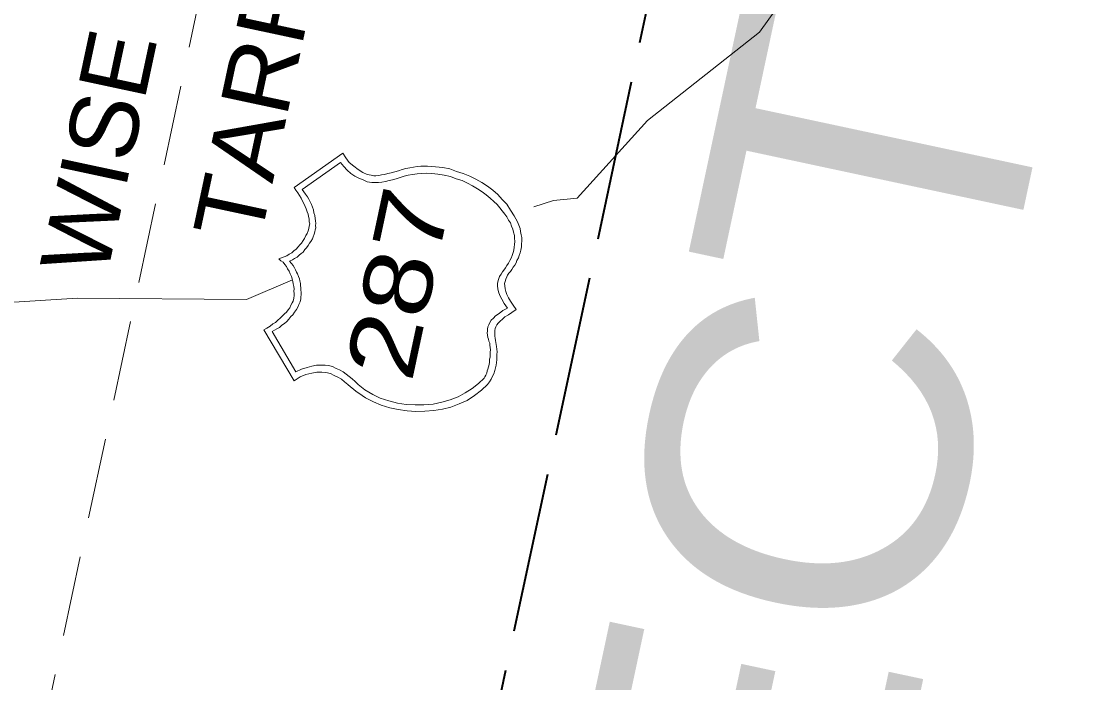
# Model space of a CAD drawing. Extents: x 2363411 to 2369126, y 6976878 to 6988319.
# Drawn here: x 2365792.5 to 2365871.2, y 6977067.2 to 6977116.7 of the extents above; entities that cross this region are included whole.
import ezdxf

# ---------------------------------------------------------------- set-up
doc = ezdxf.new("R2010")
doc.units = 0
doc.header["$LTSCALE"] = 2
doc.linetypes.add('LONG_DASHED', pattern=[7.5, 6, -1.5])
doc.linetypes.add('MEDIUM_DASHED', pattern=[4.5, 3, -1.5])
doc.layers.add('62', color=7, linetype='Continuous', lineweight=13)
doc.layers.add('63', color=7, linetype='Continuous', lineweight=13)

msp = doc.modelspace()

# ---------------------------------------------------------------- linework, layer by layer
at = {"layer": '62', "linetype": 'MEDIUM_DASHED'}
msp.add_line((2365864.629, 6977393.47), (2365770.962, 6976955.102), dxfattribs=at)
at = {"layer": '62'}
for p, q in [((2365832.332, 6977103.289), (2365830.869, 6977102.796)), ((2365809.372, 6977095.885), (2365812.816, 6977097.358))]:
    msp.add_line(p, q, dxfattribs=at)
for points in [[(2365832.332, 6977103.289), (2365834.117, 6977103.46), (2365839.362, 6977109.264), (2365847.746, 6977115.874), (2365856.16, 6977127.585), (2365865.436, 6977136.53), (2365870.448, 6977142.431)], [(2365812.924, 6977089.788), (2365810.657, 6977093.611), (2365810.894, 6977093.742), (2365811.129, 6977093.878), (2365811.326, 6977094.044), (2365811.534, 6977094.158), (2365811.706, 6977094.329), (2365811.878, 6977094.477), (2365812.048, 6977094.624), (2365812.222, 6977094.794), (2365812.366, 6977094.927), (2365812.474, 6977095.11), (2365812.598, 6977095.264), (2365812.685, 6977095.454), (2365812.789, 6977095.615), (2365812.865, 6977095.761), (2365812.912, 6977095.982), (2365812.933, 6977096.184), (2365812.94, 6977096.32), (2365812.906, 6977096.49), (2365812.924, 6977096.671), (2365812.917, 6977096.854), (2365812.864, 6977097.047), (2365812.832, 6977097.218), (2365812.781, 6977097.413), (2365812.731, 6977097.608), (2365812.632, 6977097.79), (2365812.56, 6977097.99), (2365812.441, 6977098.177), (2365812.362, 6977098.355), (2365812.231, 6977098.496), (2365812.107, 6977098.663), (2365811.943, 6977098.766), (2365811.79, 6977098.911), (2365811.989, 6977098.985), (2365812.191, 6977099.056), (2365812.393, 6977099.152), (2365812.554, 6977099.255), (2365812.763, 6977099.372), (2365812.91, 6977099.522), (2365813.077, 6977099.65), (2365813.224, 6977099.805), (2365813.349, 6977099.96), (2365813.494, 6977100.091), (2365813.605, 6977100.296), (2365813.703, 6977100.435), (2365813.799, 6977100.67), (2365813.9, 6977100.808), (2365813.989, 6977101.02), (2365814.026, 6977101.196), (2365814.061, 6977101.35), (2365814.104, 6977101.548), (2365814.064, 6977101.693), (2365814.063, 6977101.902), (2365814.012, 6977102.097), (2365813.98, 6977102.263), (2365813.902, 6977102.442), (2365813.835, 6977102.663), (2365813.757, 6977102.841), (2365813.663, 6977103.045), (2365813.565, 6977103.229), (2365813.452, 6977103.458), (2365813.331, 6977103.645), (2365813.214, 6977103.854), (2365813.071, 6977104.045), (2365812.933, 6977104.26), (2365816.564, 6977106.82), (2365816.79, 6977106.471), (2365817.058, 6977106.115), (2365817.389, 6977105.838), (2365817.729, 6977105.606), (2365818.071, 6977105.371), (2365818.409, 6977105.231), (2365818.695, 6977105.168), (2365818.893, 6977105.126), (2365819.057, 6977105.136), (2365819.27, 6977105.16), (2365819.459, 6977105.189), (2365819.699, 6977105.23), (2365819.943, 6977105.29), (2365820.184, 6977105.355), (2365820.455, 6977105.438), (2365820.746, 6977105.511), (2365821.019, 6977105.592), (2365821.289, 6977105.671), (2365821.597, 6977105.722), (2365821.863, 6977105.78), (2365822.146, 6977105.813), (2365822.406, 6977105.848), (2365822.664, 6977105.862), (2365822.914, 6977105.854), (2365823.5, 6977105.798), (2365824.065, 6977105.747), (2365824.572, 6977105.639), (2365825.087, 6977105.459), (2365825.586, 6977105.307), (2365826.071, 6977105.11), (2365826.527, 6977104.875), (2365826.978, 6977104.617), (2365827.409, 6977104.364), (2365827.801, 6977104.049)], [(2365828.322, 6977102.721), (2365828.122, 6977102.97), (2365827.874, 6977103.205), (2365827.605, 6977103.449), (2365827.31, 6977103.698), (2365826.991, 6977103.925), (2365826.65, 6977104.158), (2365826.282, 6977104.373), (2365825.908, 6977104.57), (2365825.493, 6977104.773), (2365825.061, 6977104.914), (2365824.635, 6977105.073), (2365824.152, 6977105.176), (2365823.683, 6977105.252), (2365823.235, 6977105.303), (2365822.851, 6977105.338), (2365822.474, 6977105.304), (2365822.126, 6977105.286), (2365821.791, 6977105.221), (2365821.458, 6977105.175), (2365821.166, 6977105.1), (2365820.869, 6977105.002), (2365820.572, 6977104.904), (2365820.304, 6977104.827), (2365820.035, 6977104.767), (2365819.77, 6977104.707), (2365819.503, 6977104.65), (2365819.248, 6977104.635), (2365819.014, 6977104.617), (2365818.741, 6977104.629), (2365818.408, 6977104.677), (2365818.09, 6977104.815), (2365817.774, 6977104.952), (2365817.463, 6977105.108), (2365817.163, 6977105.312), (2365816.891, 6977105.556), (2365816.65, 6977105.834), (2365816.413, 6977106.116), (2365813.544, 6977104.105), (2365813.668, 6977103.919), (2365813.791, 6977103.752), (2365813.935, 6977103.561), (2365814.035, 6977103.38), (2365814.129, 6977103.176), (2365814.224, 6977102.972), (2365814.295, 6977102.773), (2365814.369, 6977102.573), (2365814.414, 6977102.357), (2365814.485, 6977102.155), (2365814.509, 6977101.944), (2365814.538, 6977101.751), (2365814.544, 6977101.568), (2365814.534, 6977101.409), (2365814.545, 6977101.247), (2365814.512, 6977101.094), (2365814.479, 6977100.938), (2365814.419, 6977100.766), (2365814.354, 6977100.574), (2365814.301, 6977100.424), (2365814.186, 6977100.219), (2365814.088, 6977100.078), (2365813.985, 6977099.919), (2365813.854, 6977099.738), (2365813.734, 6977099.604), (2365813.604, 6977099.423), (2365813.464, 6977099.314), (2365813.321, 6977099.185), (2365813.152, 6977099.035), (2365812.969, 6977098.935), (2365812.809, 6977098.832), (2365812.581, 6977098.744), (2365812.732, 6977098.573), (2365812.856, 6977098.409), (2365812.961, 6977098.248), (2365813.042, 6977098.093), (2365813.097, 6977097.92), (2365813.182, 6977097.787), (2365813.258, 6977097.589), (2365813.338, 6977097.431), (2365813.351, 6977097.269), (2365813.401, 6977097.074), (2365813.415, 6977096.932), (2365813.445, 6977096.741), (2365813.432, 6977096.582), (2365813.467, 6977096.415), (2365813.45, 6977096.235), (2365813.441, 6977096.075), (2365813.43, 6977095.918), (2365813.383, 6977095.697), (2365813.295, 6977095.509), (2365813.204, 6977095.3), (2365813.1, 6977095.136), (2365812.966, 6977094.933), (2365812.831, 6977094.731), (2365812.688, 6977094.604), (2365812.532, 6977094.406), (2365812.378, 6977094.233), (2365812.208, 6977094.083), (2365812.023, 6977093.963), (2365811.848, 6977093.792), (2365811.639, 6977093.677)], [(2365827.801, 6977104.049), (2365828.167, 6977103.719), (2365828.502, 6977103.349), (2365828.841, 6977102.998), (2365829.114, 6977102.551), (2365829.396, 6977102.145), (2365829.64, 6977101.678), (2365829.748, 6977101.426), (2365829.837, 6977101.198), (2365829.878, 6977100.961), (2365829.92, 6977100.723), (2365829.966, 6977100.506), (2365829.964, 6977100.276), (2365829.954, 6977100.024), (2365829.936, 6977099.823), (2365829.906, 6977099.574), (2365829.835, 6977099.358), (2365829.771, 6977099.165), (2365829.711, 6977098.994), (2365829.6, 6977098.791), (2365829.538, 6977098.618), (2365829.436, 6977098.454), (2365829.31, 6977098.298), (2365829.228, 6977098.132), (2365829.124, 6977097.97), (2365829.007, 6977097.856), (2365828.904, 6977097.694), (2365828.854, 6977097.57), (2365828.774, 6977097.401), (2365828.713, 6977097.228), (2365828.681, 6977097.077), (2365828.686, 6977096.89), (2365828.711, 6977096.678), (2365828.783, 6977096.481), (2365828.85, 6977096.258), (2365828.979, 6977096.001), (2365829.11, 6977095.742), (2365829.319, 6977095.444), (2365829.551, 6977095.12), (2365829.23, 6977094.911), (2365828.963, 6977094.739), (2365828.701, 6977094.586), (2365828.521, 6977094.395), (2365828.356, 6977094.267), (2365828.208, 6977094.116), (2365828.11, 6977093.976), (2365828.035, 6977093.83), (2365827.983, 6977093.704), (2365827.951, 6977093.55), (2365827.944, 6977093.414), (2365827.956, 6977093.25), (2365827.954, 6977093.136), (2365827.964, 6977092.974), (2365827.997, 6977092.804), (2365828.014, 6977092.663), (2365828.05, 6977092.516), (2365828.062, 6977092.352), (2365828.091, 6977092.162), (2365828.114, 6977091.952), (2365828.099, 6977091.772), (2365828.101, 6977091.565), (2365828.102, 6977091.354), (2365828.086, 6977091.173), (2365828.04, 6977090.956), (2365827.997, 6977090.756), (2365827.955, 6977090.559), (2365827.881, 6977090.319), (2365827.773, 6977090.138), (2365827.683, 6977089.926), (2365827.545, 6977089.722), (2365827.391, 6977089.526), (2365826.951, 6977089.092), (2365826.43, 6977088.696), (2365825.87, 6977088.333), (2365825.283, 6977088.068), (2365824.657, 6977087.834), (2365824.046, 6977087.664), (2365823.385, 6977087.578), (2365822.704, 6977087.515), (2365822.032, 6977087.497), (2365821.396, 6977087.541), (2365820.727, 6977087.637), (2365820.088, 6977087.773), (2365819.441, 6977087.981), (2365818.869, 6977088.218), (2365818.27, 6977088.53), (2365817.768, 6977088.87), (2365817.565, 6977089.004), (2365817.368, 6977089.16), (2365817.155, 6977089.345), (2365816.943, 6977089.527), (2365816.705, 6977089.717), (2365816.471, 6977089.906), (2365816.207, 6977090.075), (2365815.934, 6977090.203), (2365815.641, 6977090.337), (2365815.312, 6977090.405), (2365814.999, 6977090.45), (2365814.628, 6977090.437), (2365814.247, 6977090.377), (2365813.808, 6977090.266)], [(2365811.296, 6977093.472), (2365813.071, 6977090.469), (2365813.478, 6977090.658), (2365813.899, 6977090.799), (2365814.263, 6977090.883), (2365814.604, 6977090.97), (2365814.926, 6977090.97), (2365815.249, 6977090.971), (2365815.516, 6977090.936), (2365815.798, 6977090.853), (2365816.071, 6977090.726), (2365816.326, 6977090.626), (2365816.591, 6977090.477), (2365816.827, 6977090.29), (2365817.046, 6977090.127), (2365817.282, 6977089.939), (2365817.491, 6977089.733), (2365817.723, 6977089.522), (2365818.233, 6977089.114), (2365818.828, 6977088.779), (2365819.368, 6977088.504), (2365820.014, 6977088.298), (2365820.671, 6977088.133), (2365821.314, 6977088.018), (2365822, 6977087.986), (2365822.643, 6977087.988), (2365823.323, 6977088.049), (2365823.976, 6977088.186), (2365824.612, 6977088.373), (2365825.21, 6977088.587), (2365825.735, 6977088.892), (2365826.264, 6977089.215), (2365826.738, 6977089.598), (2365827.144, 6977089.996), (2365827.191, 6977090.1), (2365827.286, 6977090.219), (2365827.339, 6977090.367), (2365827.377, 6977090.543), (2365827.427, 6977090.672), (2365827.488, 6977090.843), (2365827.526, 6977091.019), (2365827.54, 6977091.198), (2365827.56, 6977091.402), (2365827.594, 6977091.556), (2365827.593, 6977091.763), (2365827.607, 6977091.944), (2365827.618, 6977092.103), (2365827.591, 6977092.293), (2365827.579, 6977092.455), (2365827.563, 6977092.6), (2365827.503, 6977092.748), (2365827.471, 6977092.916), (2365827.428, 6977093.042), (2365827.394, 6977093.209), (2365827.385, 6977093.372), (2365827.389, 6977093.508), (2365827.4, 6977093.668), (2365827.433, 6977093.822), (2365827.489, 6977093.972), (2365827.573, 6977094.16), (2365827.677, 6977094.322), (2365827.847, 6977094.47), (2365828.005, 6977094.665), (2365828.273, 6977094.839), (2365828.549, 6977095.056), (2365828.887, 6977095.237), (2365828.639, 6977095.589), (2365828.477, 6977095.9), (2365828.33, 6977096.185), (2365828.228, 6977096.458), (2365828.181, 6977096.677), (2365828.156, 6977096.889), (2365828.151, 6977097.074), (2365828.198, 6977097.293), (2365828.254, 6977097.442), (2365828.307, 6977097.595), (2365828.417, 6977097.776), (2365828.52, 6977097.938), (2365828.618, 6977098.078), (2365828.745, 6977098.237), (2365828.853, 6977098.419), (2365828.984, 6977098.597), (2365829.07, 6977098.787), (2365829.177, 6977098.971), (2365829.242, 6977099.164), (2365829.31, 6977099.38), (2365829.376, 6977099.573), (2365829.399, 6977099.797), (2365829.421, 6977100.001), (2365829.445, 6977100.225), (2365829.427, 6977100.46), (2365829.426, 6977100.667), (2365829.34, 6977100.914), (2365829.294, 6977101.132), (2365829.203, 6977101.358), (2365829.119, 6977101.605), (2365828.981, 6977101.819), (2365828.848, 6977102.056), (2365828.71, 6977102.27), (2365828.504, 6977102.498), (2365828.322, 6977102.721)], [(2365699.151, 6977072.932), (2365706.254, 6977077.099), (2365719.392, 6977081.612), (2365733.468, 6977084.605), (2365748.263, 6977083.746), (2365756.527, 6977082.672), (2365766.996, 6977084.184), (2365777.065, 6977090.499), (2365786.381, 6977095.321), (2365796.715, 6977095.988), (2365809.372, 6977095.885)], [(2365811.639, 6977093.677), (2365811.456, 6977093.577), (2365811.296, 6977093.472)], [(2365813.808, 6977090.266), (2365813.378, 6977090.082), (2365812.924, 6977089.788)]]:
    msp.add_lwpolyline(points, dxfattribs=at)
at = {"layer": '62', "linetype": 'LONG_DASHED', "lineweight": 40}
msp.add_lwpolyline([(2365804.964, 6976956.79), (2365867.37, 6976943.454), (2365903.697, 6977113.468), (2365841.291, 6977126.802), (2365804.897, 6976956.481)], dxfattribs=at)
at = {"layer": '63', "linetype": 'MEDIUM_DASHED'}
msp.add_line((2365864.629, 6977393.47), (2365770.962, 6976955.102), dxfattribs=at)
at = {"layer": '63'}
for p, q in [((2365832.332, 6977103.289), (2365830.869, 6977102.796)), ((2365809.372, 6977095.885), (2365812.816, 6977097.358))]:
    msp.add_line(p, q, dxfattribs=at)
for points in [[(2365832.332, 6977103.289), (2365834.117, 6977103.46), (2365839.362, 6977109.264), (2365847.746, 6977115.874), (2365856.16, 6977127.585), (2365865.436, 6977136.53), (2365870.448, 6977142.431)], [(2365812.924, 6977089.788), (2365810.657, 6977093.611), (2365810.894, 6977093.742), (2365811.129, 6977093.878), (2365811.326, 6977094.044), (2365811.534, 6977094.158), (2365811.706, 6977094.329), (2365811.878, 6977094.477), (2365812.048, 6977094.624), (2365812.222, 6977094.794), (2365812.366, 6977094.927), (2365812.474, 6977095.11), (2365812.598, 6977095.264), (2365812.685, 6977095.454), (2365812.789, 6977095.615), (2365812.865, 6977095.761), (2365812.912, 6977095.982), (2365812.933, 6977096.184), (2365812.94, 6977096.32), (2365812.906, 6977096.49), (2365812.924, 6977096.671), (2365812.917, 6977096.854), (2365812.864, 6977097.047), (2365812.832, 6977097.218), (2365812.781, 6977097.413), (2365812.731, 6977097.608), (2365812.632, 6977097.79), (2365812.56, 6977097.99), (2365812.441, 6977098.177), (2365812.362, 6977098.355), (2365812.231, 6977098.496), (2365812.107, 6977098.663), (2365811.943, 6977098.766), (2365811.79, 6977098.911), (2365811.989, 6977098.985), (2365812.191, 6977099.056), (2365812.393, 6977099.152), (2365812.554, 6977099.255), (2365812.763, 6977099.372), (2365812.91, 6977099.522), (2365813.077, 6977099.65), (2365813.224, 6977099.805), (2365813.349, 6977099.96), (2365813.494, 6977100.091), (2365813.605, 6977100.296), (2365813.703, 6977100.435), (2365813.799, 6977100.67), (2365813.9, 6977100.808), (2365813.989, 6977101.02), (2365814.026, 6977101.196), (2365814.061, 6977101.35), (2365814.104, 6977101.548), (2365814.064, 6977101.693), (2365814.063, 6977101.902), (2365814.012, 6977102.097), (2365813.98, 6977102.263), (2365813.902, 6977102.442), (2365813.835, 6977102.663), (2365813.757, 6977102.841), (2365813.663, 6977103.045), (2365813.565, 6977103.229), (2365813.452, 6977103.458), (2365813.331, 6977103.645), (2365813.214, 6977103.854), (2365813.071, 6977104.045), (2365812.933, 6977104.26), (2365816.564, 6977106.82), (2365816.79, 6977106.471), (2365817.058, 6977106.115), (2365817.389, 6977105.838), (2365817.729, 6977105.606), (2365818.071, 6977105.371), (2365818.409, 6977105.231), (2365818.695, 6977105.168), (2365818.893, 6977105.126), (2365819.057, 6977105.136), (2365819.27, 6977105.16), (2365819.459, 6977105.189), (2365819.699, 6977105.23), (2365819.943, 6977105.29), (2365820.184, 6977105.355), (2365820.455, 6977105.438), (2365820.746, 6977105.511), (2365821.019, 6977105.592), (2365821.289, 6977105.671), (2365821.597, 6977105.722), (2365821.863, 6977105.78), (2365822.146, 6977105.813), (2365822.406, 6977105.848), (2365822.664, 6977105.862), (2365822.914, 6977105.854), (2365823.5, 6977105.798), (2365824.065, 6977105.747), (2365824.572, 6977105.639), (2365825.087, 6977105.459), (2365825.586, 6977105.307), (2365826.071, 6977105.11), (2365826.527, 6977104.875), (2365826.978, 6977104.617), (2365827.409, 6977104.364), (2365827.801, 6977104.049)], [(2365828.322, 6977102.721), (2365828.122, 6977102.97), (2365827.874, 6977103.205), (2365827.605, 6977103.449), (2365827.31, 6977103.698), (2365826.991, 6977103.925), (2365826.65, 6977104.158), (2365826.282, 6977104.373), (2365825.908, 6977104.57), (2365825.493, 6977104.773), (2365825.061, 6977104.914), (2365824.635, 6977105.073), (2365824.152, 6977105.176), (2365823.683, 6977105.252), (2365823.235, 6977105.303), (2365822.851, 6977105.338), (2365822.474, 6977105.304), (2365822.126, 6977105.286), (2365821.791, 6977105.221), (2365821.458, 6977105.175), (2365821.166, 6977105.1), (2365820.869, 6977105.002), (2365820.572, 6977104.904), (2365820.304, 6977104.827), (2365820.035, 6977104.767), (2365819.77, 6977104.707), (2365819.503, 6977104.65), (2365819.248, 6977104.635), (2365819.014, 6977104.617), (2365818.741, 6977104.629), (2365818.408, 6977104.677), (2365818.09, 6977104.815), (2365817.774, 6977104.952), (2365817.463, 6977105.108), (2365817.163, 6977105.312), (2365816.891, 6977105.556), (2365816.65, 6977105.834), (2365816.413, 6977106.116), (2365813.544, 6977104.105), (2365813.668, 6977103.919), (2365813.791, 6977103.752), (2365813.935, 6977103.561), (2365814.035, 6977103.38), (2365814.129, 6977103.176), (2365814.224, 6977102.972), (2365814.295, 6977102.773), (2365814.369, 6977102.573), (2365814.414, 6977102.357), (2365814.485, 6977102.155), (2365814.509, 6977101.944), (2365814.538, 6977101.751), (2365814.544, 6977101.568), (2365814.534, 6977101.409), (2365814.545, 6977101.247), (2365814.512, 6977101.094), (2365814.479, 6977100.938), (2365814.419, 6977100.766), (2365814.354, 6977100.574), (2365814.301, 6977100.424), (2365814.186, 6977100.219), (2365814.088, 6977100.078), (2365813.985, 6977099.919), (2365813.854, 6977099.738), (2365813.734, 6977099.604), (2365813.604, 6977099.423), (2365813.464, 6977099.314), (2365813.321, 6977099.185), (2365813.152, 6977099.035), (2365812.969, 6977098.935), (2365812.809, 6977098.832), (2365812.581, 6977098.744), (2365812.732, 6977098.573), (2365812.856, 6977098.409), (2365812.961, 6977098.248), (2365813.042, 6977098.093), (2365813.097, 6977097.92), (2365813.182, 6977097.787), (2365813.258, 6977097.589), (2365813.338, 6977097.431), (2365813.351, 6977097.269), (2365813.401, 6977097.074), (2365813.415, 6977096.932), (2365813.445, 6977096.741), (2365813.432, 6977096.582), (2365813.467, 6977096.415), (2365813.45, 6977096.235), (2365813.441, 6977096.075), (2365813.43, 6977095.918), (2365813.383, 6977095.697), (2365813.295, 6977095.509), (2365813.204, 6977095.3), (2365813.1, 6977095.136), (2365812.966, 6977094.933), (2365812.831, 6977094.731), (2365812.688, 6977094.604), (2365812.532, 6977094.406), (2365812.378, 6977094.233), (2365812.208, 6977094.083), (2365812.023, 6977093.963), (2365811.848, 6977093.792), (2365811.639, 6977093.677)], [(2365827.801, 6977104.049), (2365828.167, 6977103.719), (2365828.502, 6977103.349), (2365828.841, 6977102.998), (2365829.114, 6977102.551), (2365829.396, 6977102.145), (2365829.64, 6977101.678), (2365829.748, 6977101.426), (2365829.837, 6977101.198), (2365829.878, 6977100.961), (2365829.92, 6977100.723), (2365829.966, 6977100.506), (2365829.964, 6977100.276), (2365829.954, 6977100.024), (2365829.936, 6977099.823), (2365829.906, 6977099.574), (2365829.835, 6977099.358), (2365829.771, 6977099.165), (2365829.711, 6977098.994), (2365829.6, 6977098.791), (2365829.538, 6977098.618), (2365829.436, 6977098.454), (2365829.31, 6977098.298), (2365829.228, 6977098.132), (2365829.124, 6977097.97), (2365829.007, 6977097.856), (2365828.904, 6977097.694), (2365828.854, 6977097.57), (2365828.774, 6977097.401), (2365828.713, 6977097.228), (2365828.681, 6977097.077), (2365828.686, 6977096.89), (2365828.711, 6977096.678), (2365828.783, 6977096.481), (2365828.85, 6977096.258), (2365828.979, 6977096.001), (2365829.11, 6977095.742), (2365829.319, 6977095.444), (2365829.551, 6977095.12), (2365829.23, 6977094.911), (2365828.963, 6977094.739), (2365828.701, 6977094.586), (2365828.521, 6977094.395), (2365828.356, 6977094.267), (2365828.208, 6977094.116), (2365828.11, 6977093.976), (2365828.035, 6977093.83), (2365827.983, 6977093.704), (2365827.951, 6977093.55), (2365827.944, 6977093.414), (2365827.956, 6977093.25), (2365827.954, 6977093.136), (2365827.964, 6977092.974), (2365827.997, 6977092.804), (2365828.014, 6977092.663), (2365828.05, 6977092.516), (2365828.062, 6977092.352), (2365828.091, 6977092.162), (2365828.114, 6977091.952), (2365828.099, 6977091.772), (2365828.101, 6977091.565), (2365828.102, 6977091.354), (2365828.086, 6977091.173), (2365828.04, 6977090.956), (2365827.997, 6977090.756), (2365827.955, 6977090.559), (2365827.881, 6977090.319), (2365827.773, 6977090.138), (2365827.683, 6977089.926), (2365827.545, 6977089.722), (2365827.391, 6977089.526), (2365826.951, 6977089.092), (2365826.43, 6977088.696), (2365825.87, 6977088.333), (2365825.283, 6977088.068), (2365824.657, 6977087.834), (2365824.046, 6977087.664), (2365823.385, 6977087.578), (2365822.704, 6977087.515), (2365822.032, 6977087.497), (2365821.396, 6977087.541), (2365820.727, 6977087.637), (2365820.088, 6977087.773), (2365819.441, 6977087.981), (2365818.869, 6977088.218), (2365818.27, 6977088.53), (2365817.768, 6977088.87), (2365817.565, 6977089.004), (2365817.368, 6977089.16), (2365817.155, 6977089.345), (2365816.943, 6977089.527), (2365816.705, 6977089.717), (2365816.471, 6977089.906), (2365816.207, 6977090.075), (2365815.934, 6977090.203), (2365815.641, 6977090.337), (2365815.312, 6977090.405), (2365814.999, 6977090.45), (2365814.628, 6977090.437), (2365814.247, 6977090.377), (2365813.808, 6977090.266)], [(2365811.296, 6977093.472), (2365813.071, 6977090.469), (2365813.478, 6977090.658), (2365813.899, 6977090.799), (2365814.263, 6977090.883), (2365814.604, 6977090.97), (2365814.926, 6977090.97), (2365815.249, 6977090.971), (2365815.516, 6977090.936), (2365815.798, 6977090.853), (2365816.071, 6977090.726), (2365816.326, 6977090.626), (2365816.591, 6977090.477), (2365816.827, 6977090.29), (2365817.046, 6977090.127), (2365817.282, 6977089.939), (2365817.491, 6977089.733), (2365817.723, 6977089.522), (2365818.233, 6977089.114), (2365818.828, 6977088.779), (2365819.368, 6977088.504), (2365820.014, 6977088.298), (2365820.671, 6977088.133), (2365821.314, 6977088.018), (2365822, 6977087.986), (2365822.643, 6977087.988), (2365823.323, 6977088.049), (2365823.976, 6977088.186), (2365824.612, 6977088.373), (2365825.21, 6977088.587), (2365825.735, 6977088.892), (2365826.264, 6977089.215), (2365826.738, 6977089.598), (2365827.144, 6977089.996), (2365827.191, 6977090.1), (2365827.286, 6977090.219), (2365827.339, 6977090.367), (2365827.377, 6977090.543), (2365827.427, 6977090.672), (2365827.488, 6977090.843), (2365827.526, 6977091.019), (2365827.54, 6977091.198), (2365827.56, 6977091.402), (2365827.594, 6977091.556), (2365827.593, 6977091.763), (2365827.607, 6977091.944), (2365827.618, 6977092.103), (2365827.591, 6977092.293), (2365827.579, 6977092.455), (2365827.563, 6977092.6), (2365827.503, 6977092.748), (2365827.471, 6977092.916), (2365827.428, 6977093.042), (2365827.394, 6977093.209), (2365827.385, 6977093.372), (2365827.389, 6977093.508), (2365827.4, 6977093.668), (2365827.433, 6977093.822), (2365827.489, 6977093.972), (2365827.573, 6977094.16), (2365827.677, 6977094.322), (2365827.847, 6977094.47), (2365828.005, 6977094.665), (2365828.273, 6977094.839), (2365828.549, 6977095.056), (2365828.887, 6977095.237), (2365828.639, 6977095.589), (2365828.477, 6977095.9), (2365828.33, 6977096.185), (2365828.228, 6977096.458), (2365828.181, 6977096.677), (2365828.156, 6977096.889), (2365828.151, 6977097.074), (2365828.198, 6977097.293), (2365828.254, 6977097.442), (2365828.307, 6977097.595), (2365828.417, 6977097.776), (2365828.52, 6977097.938), (2365828.618, 6977098.078), (2365828.745, 6977098.237), (2365828.853, 6977098.419), (2365828.984, 6977098.597), (2365829.07, 6977098.787), (2365829.177, 6977098.971), (2365829.242, 6977099.164), (2365829.31, 6977099.38), (2365829.376, 6977099.573), (2365829.399, 6977099.797), (2365829.421, 6977100.001), (2365829.445, 6977100.225), (2365829.427, 6977100.46), (2365829.426, 6977100.667), (2365829.34, 6977100.914), (2365829.294, 6977101.132), (2365829.203, 6977101.358), (2365829.119, 6977101.605), (2365828.981, 6977101.819), (2365828.848, 6977102.056), (2365828.71, 6977102.27), (2365828.504, 6977102.498), (2365828.322, 6977102.721)], [(2365699.151, 6977072.932), (2365706.254, 6977077.099), (2365719.392, 6977081.612), (2365733.468, 6977084.605), (2365748.263, 6977083.746), (2365756.527, 6977082.672), (2365766.996, 6977084.184), (2365777.065, 6977090.499), (2365786.381, 6977095.321), (2365796.715, 6977095.988), (2365809.372, 6977095.885)], [(2365811.639, 6977093.677), (2365811.456, 6977093.577), (2365811.296, 6977093.472)], [(2365813.808, 6977090.266), (2365813.378, 6977090.082), (2365812.924, 6977089.788)]]:
    msp.add_lwpolyline(points, dxfattribs=at)
at = {"layer": '63', "linetype": 'LONG_DASHED', "lineweight": 40}
msp.add_lwpolyline([(2365804.964, 6976956.79), (2365867.37, 6976943.454), (2365903.697, 6977113.468), (2365841.291, 6977126.802), (2365804.897, 6976956.481)], dxfattribs=at)

# ---------------------------------------------------------------- texts
at = {"layer": '62'}
for s, height, width, p in [('TARRANT', 5.099, 1.1, (2365810.346, 6977100.003)), ('PROJECT', 23.83, 1.1, (2365835.896, 6976954.668)), ('WISE', 5.099, 1.05, (2365798.885, 6977097.414)), ('287', 5.099, 1.25, (2365821.718, 6977089.589))]:
    msp.add_text(s, height=height, rotation=77.939, dxfattribs=dict(at, width=width)).set_placement(p)
at = {"layer": '63'}
for s, height, width, p in [('TARRANT', 5.099, 1.1, (2365810.346, 6977100.003)), ('PROJECT', 23.83, 1.1, (2365835.896, 6976954.668)), ('WISE', 5.099, 1.05, (2365798.885, 6977097.414)), ('287', 5.099, 1.25, (2365821.718, 6977089.589))]:
    msp.add_text(s, height=height, rotation=77.939, dxfattribs=dict(at, width=width)).set_placement(p)

doc.saveas('drawing.dxf')
